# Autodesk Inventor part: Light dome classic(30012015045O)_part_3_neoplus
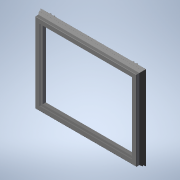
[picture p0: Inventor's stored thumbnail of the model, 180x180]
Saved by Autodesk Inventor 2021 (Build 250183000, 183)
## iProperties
Created: 2026-04
Part Number: Light dome classic(30012015045O)_part_3_neoplus
Material: Generic
Catalog Web Link: www.3dfindit.com
Description: Light dome classic_part_3_neoplus-
Vendor: KINGSPAN
Document SubType Name: Modeling
Designer: psAdmin
Manufacturer: KINGSPAN
Mass: 26077.8 g
Surface Area: 23794.2 cm^2
Volume: 26077.8 cm^3
Density: 1 g/cm^3
Appearance: PSOLRGB-255-255-255
Category: PARTsolutions
Company: KINGSPAN
Title: Light dome classic(30012015045O)_part_3_neoplus
Author: Cadenas PARTsolutions
PSOL_IDENT_0: {$CADENAS_DATA/23d-libs/kingspan_kla/light_dome_classic_neoplus/parts/part_3.prj},283 {VTYP=3D},{NB=
PSOL_IDENT_1: Light dome classic(30012015045O)_part_3_neoplus},{LINA=Light dome classic(30012015045O)_part_3_neopl
PSOL_IDENT_2: us},{NN=Light dome classic_part_3_neoplus},{DATE=20.03.2025 09:30:52},{GEOMDATE=01.07.2024 06:07:22}
PSOL_IDENT_3: ,{VERSION=},{LINEID=10},{WBVAR=LODLEVEL,L,W,DP,OP,OC},{WBNUMERIC=W}  {NB=Light dome classic(30012015
PSOL_IDENT_4: 045O)_part_3_neoplus},{LINA=Light dome classic(30012015045O)_part_3_neoplus},{KT=DUMMY},{IDNR=},{PN=
PSOL_IDENT_5: Light dome classic},{LODLEVEL=300},{L=120},{W=150},{DRIVE=1},{WX=120,150,180,240,270,300},{DP=4},{OP=
PSOL_IDENT_6: 5},{OPX='5','Pneumatic - NRWG F.6 LK'},{LX=1200},{XWX=1500},{OC=O}
NB: Light dome classic(30012015045O)_part_3_neoplus
NN: Light dome classic_part_3_neoplus
NBSYN: $PN.($LODLEVEL.$L.$W.$DP.$OP.$OC.)_part_3_neoplus
LINA: Light dome classic(30012015045O)_part_3_neoplus
CATALOG: Light + Air
PN: Light dome classic
LODLEVEL: 300
L: 120
W: 150
DP: NSHE
OP: Pneumatic - NRWG F.6 LK
OC: Open
SUPPLIER: KINGSPAN
ARTICLENO: Light dome classic(30012015045O)_part_3_neoplus
BOMINFO: Light dome classic(30012015045O)_part_3_neoplus
CREATOR: CADENAS GmbH
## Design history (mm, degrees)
sketch "Sketch_1"
  geometry: L1 (-644, 25.446)-(-644, 71.946); L2 (-644, 71.946)-(-674, 71.946); L3 (-674, 71.946)-(-674, 103.596); L4 (-674, 103.596)-(-652, 103.596); L5 (-652, 103.596)-(-652, 106.946); L6 (-652, 106.946)-(-707, 106.946); L7 (-712, 101.946)-(-712, 45.447); L8 (-712, 45.447)-(-742.031, 1.954); L9 (-740.242, 0.252)-(-737.688, 2.21); L10 (-737.688, 2.21)-(-738.863, 3.022); L11 (-738.863, 3.022)-(-721, 28.893); L12 (-721, 28.893)-(-721, 17.946); L13 (-721, 17.946)-(-679.25, 17.946); L14 (-679.25, 17.946)-(-679.25, 21.946); L15 (-679.25, 21.946)-(-681.25, 21.946); L16 (-681.25, 21.946)-(-681.25, 19.946); L17 (-681.25, 19.946)-(-686.75, 19.946); L18 (-686.75, 19.946)-(-686.75, 23.946); L19 (-686.75, 23.946)-(-671.2, 23.946); L20 (-671.2, 23.946)-(-671.2, 25.446); L21 (-671.2, 25.446)-(-644, 25.446); A1 r 5 centre (-707, 101.946) between (-707, 106.946) and (-712, 101.946); A2 r 1.25 centre (-741.002, 1.244) between (-742.031, 1.954) and (-740.242, 0.252)
  constraints: 42 end point, 4 point on circle, 2 centre point
extrude "Extrusion1" join sketch "Sketch_1" stored distance "d0" = 2400; taper "d1" = 0 deg
sketch "Sketch_2"
  geometry: L1 (502, 106.946)-(502, 103.596); L2 (502, 103.596)-(524, 103.596); L3 (524, 103.596)-(524, 71.946); L4 (524, 71.946)-(494, 71.946); L5 (494, 71.946)-(494, 25.446); L6 (494, 25.446)-(521.2, 25.446); L7 (521.2, 25.446)-(521.2, 23.946); L8 (521.2, 23.946)-(536.75, 23.946); L9 (536.75, 23.946)-(536.75, 19.946); L10 (536.75, 19.946)-(531.25, 19.946); L11 (531.25, 19.946)-(531.25, 21.946); L12 (531.25, 21.946)-(529.25, 21.946); L13 (529.25, 21.946)-(529.25, 17.946); L14 (529.25, 17.946)-(571, 17.946); L15 (571, 17.946)-(571, 28.893); L16 (571, 28.893)-(588.863, 3.022); L17 (588.863, 3.022)-(587.688, 2.21); L18 (587.688, 2.21)-(590.242, 0.252); L19 (592.031, 1.954)-(562, 45.447); L20 (562, 45.447)-(562, 101.946); L21 (557, 106.946)-(502, 106.946); A1 r 1.25 centre (591.002, 1.244) between (590.242, 0.252) and (592.031, 1.954); A2 r 5 centre (557, 101.946) between (562, 101.946) and (557, 106.946)
  constraints: 42 end point, 4 point on circle, 2 centre point
extrude "Extrusion2" join sketch "Sketch_2" stored distance "d2" = 3000; taper "d3" = 0 deg
sketch "Sketch_3"
  geometry: L1 (742.031, 1.954)-(712, 45.447); L2 (712, 45.447)-(712, 101.946); L3 (707, 106.946)-(652, 106.946); L4 (652, 106.946)-(652, 103.596); L5 (652, 103.596)-(674, 103.596); L6 (674, 103.596)-(674, 71.946); L7 (674, 71.946)-(644, 71.946); L8 (644, 71.946)-(644, 25.446); L9 (644, 25.446)-(671.2, 25.446); L10 (671.2, 25.446)-(671.2, 23.946); L11 (671.2, 23.946)-(686.75, 23.946); L12 (686.75, 23.946)-(686.75, 19.946); L13 (686.75, 19.946)-(681.25, 19.946); L14 (681.25, 19.946)-(681.25, 21.946); L15 (681.25, 21.946)-(679.25, 21.946); L16 (679.25, 21.946)-(679.25, 17.946); L17 (679.25, 17.946)-(721, 17.946); L18 (721, 17.946)-(721, 28.893); L19 (721, 28.893)-(738.863, 3.022); L20 (738.863, 3.022)-(737.688, 2.21); L21 (737.688, 2.21)-(740.242, 0.252); A1 r 1.25 centre (741.002, 1.244) between (740.242, 0.252) and (742.031, 1.954); A2 r 5 centre (707, 101.946) between (712, 101.946) and (707, 106.946)
  constraints: 42 end point, 4 point on circle, 2 centre point
extrude "Extrusion3" join sketch "Sketch_3" stored distance "d4" = 2400; taper "d5" = 0 deg
sketch "Sketch_4"
  geometry: L1 (-502, 106.946)-(-557, 106.946); L2 (-562, 101.946)-(-562, 45.447); L3 (-562, 45.447)-(-592.031, 1.954); L4 (-590.242, 0.252)-(-587.688, 2.21); L5 (-587.688, 2.21)-(-588.863, 3.022); L6 (-588.863, 3.022)-(-571, 28.893); L7 (-571, 28.893)-(-571, 17.946); L8 (-571, 17.946)-(-529.25, 17.946); L9 (-529.25, 17.946)-(-529.25, 21.946); L10 (-529.25, 21.946)-(-531.25, 21.946); L11 (-531.25, 21.946)-(-531.25, 19.946); L12 (-531.25, 19.946)-(-536.75, 19.946); L13 (-536.75, 19.946)-(-536.75, 23.946); L14 (-536.75, 23.946)-(-521.2, 23.946); L15 (-521.2, 23.946)-(-521.2, 25.446); L16 (-521.2, 25.446)-(-494, 25.446); L17 (-494, 25.446)-(-494, 71.946); L18 (-494, 71.946)-(-524, 71.946); L19 (-524, 71.946)-(-524, 103.596); L20 (-524, 103.596)-(-502, 103.596); L21 (-502, 103.596)-(-502, 106.946); A1 r 5 centre (-557, 101.946) between (-557, 106.946) and (-562, 101.946); A2 r 1.25 centre (-591.002, 1.244) between (-592.031, 1.954) and (-590.242, 0.252)
  constraints: 42 end point, 4 point on circle, 2 centre point
extrude "Extrusion4" join sketch "Sketch_4" stored distance "d6" = 3000; taper "d7" = 0 deg
sketch "Sketch_5"
  geometry: L1 (-652, 156.946)-(-1500, 156.946); L2 (-1500, 156.946)-(-1500, -32.054); L3 (-1500, -32.054)-(-741.002, -32.054); L4 (-741.002, -32.054)-(-741.002, -0.006); L5 (-742.031, 1.954)-(-712, 45.447); L6 (-712, 45.447)-(-712, 101.946); L7 (-707, 106.946)-(-652, 106.946); L8 (-652, 106.946)-(-652, 156.946); A1 r 1.25 centre (-741.002, 1.244) between (-742.031, 1.954) and (-741.002, -0.006); A2 r 5 centre (-707, 101.946) between (-707, 106.946) and (-712, 101.946)
  constraints: 16 end point, 4 point on circle, 2 centre point
extrude "Extrusion5" cut sketch "Sketch_5" stored distance "d8" = 2400; taper "d9" = 0 deg
sketch "Sketch_6"
  geometry: L1 (1500, 156.946)-(652, 156.946); L2 (652, 156.946)-(652, 106.946); L3 (652, 106.946)-(707, 106.946); L4 (712, 101.946)-(712, 45.447); L5 (712, 45.447)-(742.031, 1.954); L6 (741.002, -0.006)-(741.002, -32.054); L7 (741.002, -32.054)-(1500, -32.054); L8 (1500, -32.054)-(1500, 156.946); A1 r 5 centre (707, 101.946) between (712, 101.946) and (707, 106.946); A2 r 1.25 centre (741.002, 1.244) between (741.002, -0.006) and (742.031, 1.954)
  constraints: 16 end point, 4 point on circle, 2 centre point
extrude "Extrusion6" cut sketch "Sketch_6" stored distance "d10" = 2400; taper "d11" = 0 deg
sketch "Sketch_7"
  geometry: L1 (1200, 156.946)-(502, 156.946); L2 (502, 156.946)-(502, 106.946); L3 (502, 106.946)-(557, 106.946); L4 (562, 101.946)-(562, 45.447); L5 (562, 45.447)-(592.031, 1.954); L6 (591.002, -0.006)-(591.002, -32.054); L7 (591.002, -32.054)-(1200, -32.054); L8 (1200, -32.054)-(1200, 156.946); A1 r 5 centre (557, 101.946) between (562, 101.946) and (557, 106.946); A2 r 1.25 centre (591.002, 1.244) between (591.002, -0.006) and (592.031, 1.954)
  constraints: 16 end point, 4 point on circle, 2 centre point
extrude "Extrusion7" cut sketch "Sketch_7" stored distance "d12" = 3000; taper "d13" = 0 deg
sketch "Sketch_8"
  geometry: L1 (-1200, 156.946)-(-1200, -32.054); L2 (-1200, -32.054)-(-591.002, -32.054); L3 (-591.002, -32.054)-(-591.002, -0.006); L4 (-592.031, 1.954)-(-562, 45.447); L5 (-562, 45.447)-(-562, 101.946); L6 (-557, 106.946)-(-502, 106.946); L7 (-502, 106.946)-(-502, 156.946); L8 (-502, 156.946)-(-1200, 156.946); A1 r 1.25 centre (-591.002, 1.244) between (-592.031, 1.954) and (-591.002, -0.006); A2 r 5 centre (-557, 101.946) between (-557, 106.946) and (-562, 101.946)
  constraints: 16 end point, 4 point on circle, 2 centre point
extrude "Extrusion8" cut sketch "Sketch_8" stored distance "d14" = 3000; taper "d15" = 0 deg
sketch "Sketch_9"
  geometry: L1 (-707, 34.19)-(-707, 71.429); L2 (-707, 71.429)-(-733.061, 32.792); L3 (-731.277, 31.71)-(-728.348, 34.19); L4 (-728.348, 34.19)-(-707, 34.19); A1 r 1.1 centre (-731.988, 32.55) between (-733.061, 32.792) and (-731.277, 31.71)
  constraints: 8 end point, 2 point on circle, 1 centre point
extrude "Extrusion9" join sketch "Sketch_9" stored distance "d16" = 2400; taper "d17" = 0 deg
sketch "Sketch_10"
  geometry: L1 (557, 71.429)-(557, 34.19); L2 (557, 34.19)-(578.348, 34.19); L3 (578.348, 34.19)-(581.277, 31.71); L4 (583.061, 32.792)-(557, 71.429); A1 r 1.1 centre (581.988, 32.55) between (581.277, 31.71) and (583.061, 32.792)
  constraints: 8 end point, 2 point on circle, 1 centre point
extrude "Extrusion10" join sketch "Sketch_10" stored distance "d18" = 3000; taper "d19" = 0 deg
sketch "Sketch_11"
  geometry: L1 (733.061, 32.792)-(707, 71.429); L2 (707, 71.429)-(707, 34.19); L3 (707, 34.19)-(728.348, 34.19); L4 (728.348, 34.19)-(731.277, 31.71); A1 r 1.1 centre (731.988, 32.55) between (731.277, 31.71) and (733.061, 32.792)
  constraints: 8 end point, 2 point on circle, 1 centre point
extrude "Extrusion11" join sketch "Sketch_11" stored distance "d20" = 2400; taper "d21" = 0 deg
sketch "Sketch_12"
  geometry: L1 (-557, 71.429)-(-583.061, 32.792); L2 (-581.277, 31.71)-(-578.348, 34.19); L3 (-578.348, 34.19)-(-557, 34.19); L4 (-557, 34.19)-(-557, 71.429); A1 r 1.1 centre (-581.988, 32.55) between (-583.061, 32.792) and (-581.277, 31.71)
  constraints: 8 end point, 2 point on circle, 1 centre point
extrude "Extrusion12" join sketch "Sketch_12" stored distance "d22" = 3000; taper "d23" = 0 deg
sketch "Sketch_13"
  geometry: L1 (-712, 74.016)-(-2231.988, 74.016); L2 (-2231.988, 74.016)-(-2231.988, 27.946); L3 (-2231.988, 27.946)-(-731.988, 27.946); L4 (-731.988, 27.946)-(-731.988, 31.45); L5 (-733.061, 32.792)-(-712, 64.016); L6 (-712, 64.016)-(-712, 74.016); A1 r 1.1 centre (-731.988, 32.55) between (-733.061, 32.792) and (-731.988, 31.45)
  constraints: 12 end point, 2 point on circle, 1 centre point
extrude "Extrusion13" cut sketch "Sketch_13" stored distance "d24" = 2400; taper "d25" = 0 deg
sketch "Sketch_14"
  geometry: L1 (2231.988, 27.946)-(2231.988, 74.016); L2 (2231.988, 74.016)-(712, 74.016); L3 (712, 74.016)-(712, 64.016); L4 (712, 64.016)-(733.061, 32.792); L5 (731.988, 31.45)-(731.988, 27.946); L6 (731.988, 27.946)-(2231.988, 27.946); A1 r 1.1 centre (731.988, 32.55) between (731.988, 31.45) and (733.061, 32.792)
  constraints: 12 end point, 2 point on circle, 1 centre point
extrude "Extrusion14" cut sketch "Sketch_14" stored distance "d26" = 2400; taper "d27" = 0 deg
sketch "Sketch_15"
  geometry: L1 (1781.988, 74.016)-(562, 74.016); L2 (562, 74.016)-(562, 64.016); L3 (562, 64.016)-(583.061, 32.792); L4 (581.988, 31.45)-(581.988, 27.946); L5 (581.988, 27.946)-(1781.988, 27.946); L6 (1781.988, 27.946)-(1781.988, 74.016); A1 r 1.1 centre (581.988, 32.55) between (581.988, 31.45) and (583.061, 32.792)
  constraints: 12 end point, 2 point on circle, 1 centre point
extrude "Extrusion15" cut sketch "Sketch_15" stored distance "d28" = 3000; taper "d29" = 0 deg
sketch "Sketch_16"
  geometry: L1 (-1781.988, 74.016)-(-1781.988, 27.946); L2 (-1781.988, 27.946)-(-581.988, 27.946); L3 (-581.988, 27.946)-(-581.988, 31.45); L4 (-583.061, 32.792)-(-562, 64.016); L5 (-562, 64.016)-(-562, 74.016); L6 (-562, 74.016)-(-1781.988, 74.016); A1 r 1.1 centre (-581.988, 32.55) between (-583.061, 32.792) and (-581.988, 31.45)
  constraints: 12 end point, 2 point on circle, 1 centre point
extrude "Extrusion16" cut sketch "Sketch_16" stored distance "d30" = 3000; taper "d31" = 0 deg
sketch "Sketch_17"
  geometry: L1 (-17.946, 571.802)-(-17.946, 549.665); L2 (-17.946, 549.665)-(-16.1, 545.05); L3 (-16.1, 545.05)-(-14.243, 545.793); L4 (-14.243, 545.793)-(-15.946, 550.05); L5 (-15.946, 550.05)-(-15.946, 570.837); L6 (-15.946, 570.837)-(7.12, 589.184); L7 (6.644, 587.499)-(4.764, 586.817); L8 (5.875, 590.749)-(-17.946, 571.802); A1 r 1.5 centre (8.054, 588.01) between (6.644, 587.499) and (7.12, 589.184); A2 r 3.5 centre (8.054, 588.01) between (4.764, 586.817) and (5.875, 590.749)
  constraints: 16 end point, 4 point on circle, 2 centre point
extrude "Extrusion17" join sketch "Sketch_17" distance "d32" = 70; taper "d33" = 0 deg
sketch "Sketch_18"
  geometry: L1 (-17.946, 571.802)-(-17.946, 549.665); L2 (-17.946, 549.665)-(-16.1, 545.05); L3 (-16.1, 545.05)-(-14.243, 545.793); L4 (-14.243, 545.793)-(-15.946, 550.05); L5 (-15.946, 550.05)-(-15.946, 570.837); L6 (-15.946, 570.837)-(7.12, 589.184); L7 (6.644, 587.499)-(4.764, 586.817); L8 (5.875, 590.749)-(-17.946, 571.802); A1 r 1.5 centre (8.054, 588.01) between (6.644, 587.499) and (7.12, 589.184); A2 r 3.5 centre (8.054, 588.01) between (4.764, 586.817) and (5.875, 590.749)
  constraints: 16 end point, 4 point on circle, 2 centre point
extrude "Extrusion18" join sketch "Sketch_18" distance "d34" = 70; taper "d35" = 0 deg
sketch "Sketch_19"
  geometry: L1 (-15.946, 611.757)-(16.193, 573.455); L2 (16.193, 573.455)-(31.514, 586.311); L3 (31.514, 586.311)-(-0.625, 624.613); L4 (-0.625, 624.613)-(-15.946, 611.757)
  constraints: 8 end point
extrude "Extrusion19" cut sketch "Sketch_19" stored distance "d36" = 38; taper "d37" = 0 deg
sketch "Sketch_20"
  geometry: L1 (-15.946, 611.757)-(16.193, 573.455); L2 (16.193, 573.455)-(31.514, 586.311); L3 (31.514, 586.311)-(-0.625, 624.613); L4 (-0.625, 624.613)-(-15.946, 611.757)
  constraints: 8 end point
extrude "Extrusion20" cut sketch "Sketch_20" stored distance "d38" = 38; taper "d39" = 0 deg
sketch "Sketch_21"
  geometry: L1 (-609.411, -2.354)-(-587.41, -2.354); L2 (-587.41, -2.354)-(-587.41, 8.646); L3 (-587.41, 8.646)-(-585.722, 11.091); L4 (-585.722, 11.091)-(-591.711, 19.644); A1 r 20 centre (-591.411, -0.354) between (-591.711, 19.644) and (-611.411, -0.354); A2 r 2 centre (-609.411, -0.354) between (-611.411, -0.354) and (-609.411, -2.354)
  constraints: 8 end point, 4 point on circle, 2 centre point
extrude "Extrusion21" join sketch "Sketch_21" stored distance "d40" = 41; taper "d41" = 0 deg
node "IP_3_XY"
node "IP_3_YZ"
node "IP_3_ZX"
node "IP_3_X"
node "IP_3_Y"
node "IP_3_Z"
node "IP_3_Center"
node "IP_for_part_11_1_XY"
node "IP_for_part_11_1_YZ"
node "IP_for_part_11_1_ZX"
node "IP_for_part_11_1_X"
node "IP_for_part_11_1_Y"
node "IP_for_part_11_1_Z"
node "IP_for_part_11_1_Center"
node "IP_for_part_4_XY"
node "IP_for_part_4_YZ"
node "IP_for_part_4_ZX"
node "IP_for_part_4_X"
node "IP_for_part_4_Y"
node "IP_for_part_4_Z"
node "IP_for_part_4_Center"
node "IP_for_part_5_XY"
node "IP_for_part_5_YZ"
node "IP_for_part_5_ZX"
node "IP_for_part_5_X"
node "IP_for_part_5_Y"
node "IP_for_part_5_Z"
node "IP_for_part_5_Center"
node "IP_for_part_6_XY"
node "IP_for_part_6_YZ"
node "IP_for_part_6_ZX"
node "IP_for_part_6_X"
node "IP_for_part_6_Y"
node "IP_for_part_6_Z"
node "IP_for_part_6_Center"
body "Solid1"
other parameters: "d42" = 0, "d43" = 0, "d44" = 0
